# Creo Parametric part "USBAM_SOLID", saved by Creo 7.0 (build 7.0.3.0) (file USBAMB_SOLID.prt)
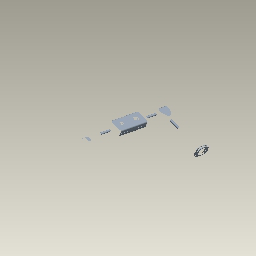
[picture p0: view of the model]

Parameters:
  PTC_COMMON_NAME = "usba_solid.prt"
  PTC_WM_REVISION = "A"
  PTC_WM_ITERATION = "1"
  PTC_WM_VERSION = "A.1"
  PTC_WM_LIFECYCLE_STATE = "Concept"
  PTC_WM_LIFECYCLE = "Life Cycle Schema Type 1"
  PTC_WM_CREATED_BY = "Mike Minsterketter"
  PTC_WM_CREATED_ON = "2022-02-24"
  PTC_WM_MODIFIED_BY = "Mike Minsterketter"
  PTC_WM_MODIFIED_ON = "2022-03-07"
  PDMREV = "A.1+"
  PDMRL = "Concept"
  PROI_REVISION = "A"
  PROI_VERSION = "1+"
  PROI_RELEASE = "Concept"
  COPY_GEOM_ORIGIN_TYPE = "Part"

Created from: USBA_SOLID.PRT

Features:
  1. datum plane "RIGHT"
  2. datum plane "TOP"
  3. datum plane "FRONT"
  4. coordinate system
  5. datum axis
  6. datum axis
  7. datum axis
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
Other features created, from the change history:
  mirror "Mirror 3"
  extrusion "Extrude 1 (2)"
  curve "Copy 1"
  feature "Copy 1" (2 times)
  feature "Extend 1" (2 times)
  feature "Extend 2" (2 times)
  feature "Extrude 2"
  patch "Solidify 5"
  feature "Copy 2"
  patch "Solidify 6"
  planar section "B"
  extrusion "Extrude 2"
  feature "Copy 3"
  feature "Extend 3"
  fill "Fill 8"
  feature "Merge 10"
  patch "Solidify 7"
  feature "Copy 4"
  feature "Extend 4"
  fill "Fill 9"
  feature "Merge 11" (2 times)
  feature "Offset Geometry 1"
  coordinate system "CS1"
  coordinate system "CS2"
  imported feature "Import Feature id 11292"
  imported feature "Import Feature id 21227"
  imported feature "Import Feature id 28479"

Other named items: X-AXES, Y-AXES, Z-AXES, CS0

Layers: .WHITE_HOLE, ANNOTATIONS, AXES, COSMETICS, CSYS, CURVES, EXT_COPY_GEOM, PLANES, POINTS, PUBLISHED_GEOM, QUILTS, SOLIDS, STARTUP

Notes: NOT SPECIFIED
